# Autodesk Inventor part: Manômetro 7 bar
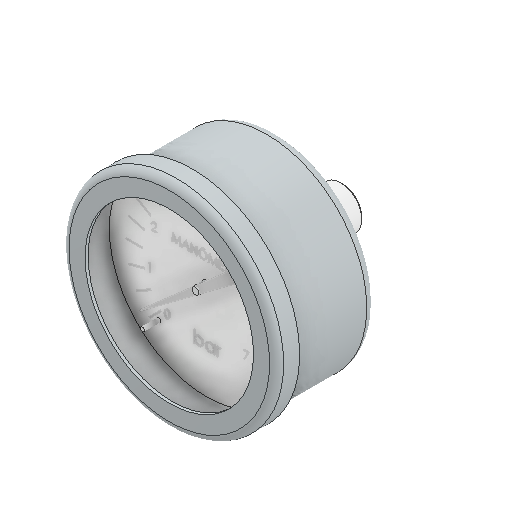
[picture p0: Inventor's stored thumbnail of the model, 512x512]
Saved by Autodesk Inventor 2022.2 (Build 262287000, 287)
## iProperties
Created: 2009-08
Part Number: Manômetro 7 bar
Material: Materiais Bomval|AISI 316
Document SubType Name: Modeling
Designer: 18907419
Density: 8 g/cm^3
Appearance: Default
Author: 18907419
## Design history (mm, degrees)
feature "Solido1"
feature "Solido2:1"
feature "Solido3:1"
feature "Solido4:1"
feature "Solido5:1"
feature "Solido6:1"
feature "Solido7:1"
feature "Solido8:1"
feature "Solido9:1"
feature "Solido10:1"
feature "Solido11:1"
feature "Solido12:1"
feature "Solido13:1"
feature "Solido14:1"
feature "Solido15:1"
feature "Solido16:1"
feature "Solido17:1"
feature "Solido18:1"
feature "Solido19:1"
feature "Solido20:1"
feature "Solido21:1"
feature "Solido22:1"
feature "Solido23:1"
feature "Solido24:1"
feature "Solido25:1"
feature "Solido26:1"
feature "Solido27:1"
feature "Solido28:1"
feature "Solido29:1"
feature "Solido30:1"
feature "Solido31:1"
feature "Solido32:1"
feature "Solido33:1"
feature "Solido34:1"
feature "Solido35:1"
feature "Solido36:1"
feature "Solido37:1"
feature "Solido38:1"
feature "Solido39:1"
feature "Solido40:1"
feature "Solido41:1"
feature "Solido42:1"
feature "Solido43:1"
feature "Solido44:1"
feature "Solido45:1"
feature "Solido46:1"
feature "Solido47:1"
feature "Solido48:1"
feature "Solido49:1"
node "Solido2"
node "Solido3"
node "Solido4"
node "Solido5"
node "Solido6"
node "Solido7"
node "Solido8"
node "Solido9"
node "Solido10"
node "Solido11"
node "Solido12"
node "Solido13"
node "Solido14"
node "Solido15"
node "Solido16"
node "Solido17"
node "Solido18"
node "Solido19"
node "Solido20"
node "Solido21"
node "Solido22"
node "Solido23"
node "Solido24"
node "Solido25"
node "Solido26"
node "Solido27"
node "Solido28"
node "Solido29"
node "Solido30"
node "Solido31"
node "Solido32"
node "Solido33"
node "Solido34"
node "Solido35"
node "Solido36"
node "Solido37"
node "Solido38"
node "Solido39"
node "Solido40"
node "Solido41"
node "Solido42"
node "Solido43"
node "Solido44"
node "Solido45"
node "Solido46"
node "Solido47"
node "Solido48"
node "Solido49"
node "Solido50"
